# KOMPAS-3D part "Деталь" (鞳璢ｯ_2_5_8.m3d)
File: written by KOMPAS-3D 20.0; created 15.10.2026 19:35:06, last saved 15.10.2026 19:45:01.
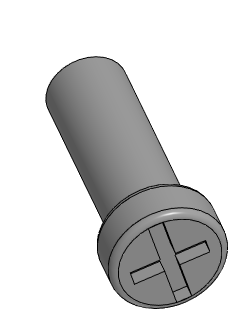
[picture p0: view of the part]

Document properties: Полное имя файла: D:\myProjects\Progect_esp32\box_compas\прочее\шуруп_2_5_8.m3d

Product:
- Part/product: Деталь
    Масса: 0.000439598
  - Body: Тело 1
      Масса: 0.000433564

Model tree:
1. Эскиз:1
2. Элемент выдавливания:1
     Расстояние 1 = 1.6
3. Эскиз:2  (with: Элемент выдавливания:1)
4. Элемент выдавливания:2
     Расстояние 1 = 8
5. Фаска:1  (with: Элемент выдавливания:2)
     Угол = 45; Длина 1 = 1; Длина 2 = 1
6. Скругление:1  (with: Элемент выдавливания:1)
     Радиус = 0.25
7. Эскиз:3  (with: Элемент выдавливания:1, Скругление:1)
8. Элемент выдавливания:3
     Расстояние 2 = 0.5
